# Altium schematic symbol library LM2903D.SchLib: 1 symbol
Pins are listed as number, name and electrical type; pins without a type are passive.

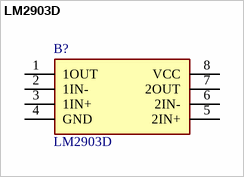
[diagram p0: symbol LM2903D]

## LM2903D
designator B?
LM2903DG4, Dual Comparator Open Collector 1.3s 2-kanalers 3, 5, 9, 12, 15, 18, 24, 28V 8-Pin SOIC; Manufacturer_Name: Texas Instruments; Geometry.Height: 1.75mm
footprint SOIC127P600X175-8N
pins: 1 1OUT, 2 1IN-, 3 1IN+, 4 GND, 5 2IN+, 6 2IN-, 7 2OUT, 8 VCC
